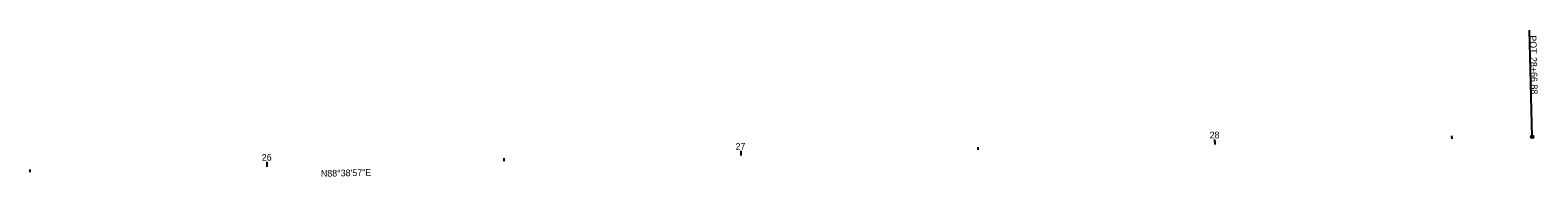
# Model space of a CAD drawing. Extents: x 2273904 to 2275373, y 654575 to 654883.
# Drawn here: x 2275055.2 to 2275373.2, y 654700.8 to 654731.7 of the extents above; entities that cross this region are included whole.
import ezdxf

# ---------------------------------------------------------------- set-up
doc = ezdxf.new("R2010")
doc.units = 0
for name, color, linetype in [('DR_P_Headwall', 7, 'Continuous'), ('DR_P_Storm_Sewer', 7, 'Continuous'), ('GE_X_Alignment_1000_Stations', 7, 'Continuous'), ('GE_X_Alignment_500_Stations', 7, 'Continuous'), ('PV_P_Drive', 7, 'Continuous')]:
    doc.layers.add(name, color=color, linetype=linetype)

msp = doc.modelspace()

# ---------------------------------------------------------------- linework, layer by layer
at = {"layer": 'DR_P_Storm_Sewer'}
for p, q in [((2275371.97, 654709.22), (2275371.44, 654731.72)), ((2275305.11, 654707.65), (2275305.1, 654708.25)), ((2275205.14, 654705.29), (2275205.12, 654705.89)), ((2275105.17, 654702.93), (2275105.15, 654703.53))]:
    msp.add_line(p, q, dxfattribs=at)
msp.add_circle((2275371.97, 654709.22), 0.3, dxfattribs=at)
at = {"layer": 'GE_X_Alignment_1000_Stations'}
for p, q in [((2275371.97, 654709.22), (2275371.44, 654731.72)), ((2275305.11, 654707.65), (2275305.09, 654708.65)), ((2275355.1, 654708.82), (2275355.08, 654709.42)), ((2275205.14, 654705.29), (2275205.11, 654706.29)), ((2275255.12, 654706.47), (2275255.11, 654707.07)), ((2275055.18, 654701.75), (2275055.16, 654702.35)), ((2275105.17, 654702.93), (2275105.14, 654703.93)), ((2275155.15, 654704.11), (2275155.14, 654704.71))]:
    msp.add_line(p, q, dxfattribs=at)
msp.add_circle((2275371.97, 654709.22), 0.3, dxfattribs=at)
at = {"layer": 'PV_P_Drive'}
msp.add_line((2275371.97, 654709.22), (2275371.44, 654731.72), dxfattribs=at)
msp.add_circle((2275371.97, 654709.22), 0.3, dxfattribs=at)

# ---------------------------------------------------------------- texts
at = {"layer": 'DR_P_Headwall'}
msp.add_text('N88°38\'57"E', height=1.4, rotation=1.351, dxfattribs=at).set_placement((2275116.51, 654700.8))
at = {"layer": 'DR_P_Storm_Sewer'}
for s, p in [('POT', (2275371.49, 654730.61)), ('28+66.88', (2275371.6, 654726.05))]:
    msp.add_text(s, height=1.4, rotation=271.351, dxfattribs=at).set_placement(p)
at = {"layer": 'GE_X_Alignment_1000_Stations'}
for s, rotation, p in [('POT', 271.351, (2275371.49, 654730.61)), ('28+66.88', 271.351, (2275371.6, 654726.05)), ('28', 1.351, (2275303.98, 654708.89)), ('26', 1.351, (2275104.04, 654704.18)), ('27', 1.351, (2275203.98, 654706.51))]:
    msp.add_text(s, height=1.4, rotation=rotation, dxfattribs=at).set_placement(p)
at = {"layer": 'GE_X_Alignment_500_Stations'}
msp.add_text('N88°38\'57"E', height=1.4, rotation=1.351, dxfattribs=at).set_placement((2275116.51, 654700.8))
msp.add_text('N88°38\'57"E', height=1.4, rotation=1.351, dxfattribs=at).set_placement((2275116.51, 654700.8))
at = {"layer": 'PV_P_Drive'}
for s, p in [('POT', (2275371.49, 654730.61)), ('28+66.88', (2275371.6, 654726.05))]:
    msp.add_text(s, height=1.4, rotation=271.351, dxfattribs=at).set_placement(p)

doc.saveas('drawing.dxf')
